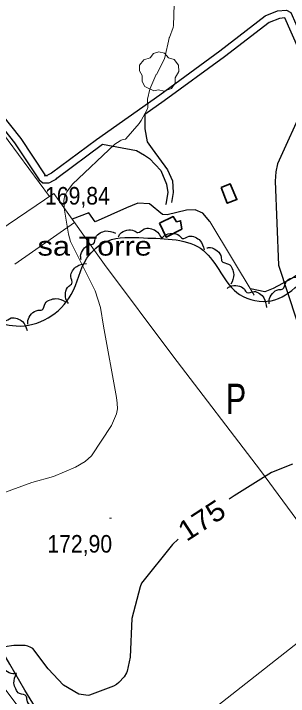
# Model space of a CAD drawing. Extents: x 480269 to 484877, y 4383588 to 4386804.
# Drawn here: x 482259.8 to 482396.3, y 4385773.1 to 4386113.1 of the extents above; entities that cross this region are included whole.
import ezdxf
from ezdxf.enums import TextEntityAlignment as Align

# ---------------------------------------------------------------- set-up
doc = ezdxf.new("R2010")
doc.units = 0
doc.header["$LTSCALE"] = 3.8
doc.linetypes.add('LONG_DASHED', pattern=[7.5, 6, -1.5])
for name, color, linetype, lineweight in [('25', 7, 'LONG_DASHED', 25), ('27', 7, 'Continuous', 25), ('29', 7, 'Continuous', 13), ('38', 7, 'Continuous', 25), ('47', 7, 'Continuous', 35), ('51', 7, 'Continuous', 13), ('7', 7, 'Continuous', 13), ('8', 7, 'Continuous', 25), ('9', 7, 'Continuous', 13)]:
    doc.layers.add(name, color=color, linetype=linetype, lineweight=lineweight)
doc.layers.add('31', color=7, linetype='Continuous')
doc.layers.add('5', color=7, linetype='Continuous')

msp = doc.modelspace()

# ---------------------------------------------------------------- linework, layer by layer
at = {"layer": '25'}
for points in [[(482357.29, 4386009.55), (482353.77, 4386013.72), (482350.05, 4386015.51), (482345.8, 4386015.31), (482336.13, 4386012.95), (482333.78, 4386013.07), (482327.37, 4386018.44), (482321.46, 4386018.81), (482315.95, 4386016.37), (482300.31, 4386009.49), (482297.2, 4386013.87), (482288.87, 4386010.87)], [(482436.54, 4386007.62), (482433.49, 4386005.54), (482426.7, 4386001.35), (482415.4, 4385992.96), (482408.62, 4385988.3), (482398.14, 4385981.17), (482388.88, 4385976.31), (482384.69, 4385974.6), (482377.49, 4385976.02)]]:
    msp.add_lwpolyline(points, dxfattribs=at)
at = {"layer": '27'}
for points in [[(482293.35, 4385990.54), (482293.11, 4385992.3), (482294.49, 4385995.84), (482297.47, 4385998.02), (482299.47, 4385998.48), (482300.59, 4386001.85), (482302.75, 4386003.92), (482305.61, 4386004.9), (482310.46, 4386003.88)], [(482311.79, 4386001.96), (482312.75, 4386003.45), (482316.08, 4386005.27), (482319.77, 4386005.02), (482321.59, 4386004.08), (482324.62, 4386005.93), (482327.6, 4386006.12), (482330.42, 4386005.03), (482333.48, 4386001.12)], [(482333.65, 4386001.49), (482334.93, 4386002.71), (482338.6, 4386003.69), (482342.12, 4386002.58), (482343.67, 4386001.23), (482347.05, 4386002.32), (482349.99, 4386001.8), (482352.48, 4386000.08), (482354.52, 4385995.56)], [(482928.34, 4385924.89), (482922.57, 4385923.15), (482885.78, 4385895.73), (482830.19, 4385870.67), (482783.99, 4385846.38), (482748.76, 4385821.32), (482700.22, 4385785.28), (482658.72, 4385739.07), (482615.66, 4385695.2), (482579.64, 4385663.09), (482560.07, 4385645.07), (482539.71, 4385649.77), (482459.85, 4385672.49), (482360.42, 4385703.82), (482306.4, 4385727.32), (482257.85, 4385789.2), (482191.3, 4385880.85), (482166.25, 4385912.96), (482169.38, 4385923.15), (482197.57, 4385932.55), (482218.71, 4385942.73), (482235.93, 4385961.53), (482260.99, 4385957.61), (482288.39, 4385973.28), (482296.22, 4385991.3), (482306.4, 4385999.91), (482324.4, 4386001.48), (482354.16, 4385995.21), (482372.16, 4385973.28), (482387.82, 4385970.15), (482414.44, 4385988.16), (482434.02, 4385990.51), (482466.12, 4385956.05), (482473.95, 4385954.08)], [(482355.85, 4385996.54), (482357.63, 4385996.64), (482361.04, 4385994.99), (482362.99, 4385991.86), (482363.29, 4385989.83), (482366.57, 4385988.45), (482368.46, 4385986.14), (482369.23, 4385983.21), (482367.84, 4385978.45)], [(482287.08, 4385968.86), (482286.05, 4385970.31), (482285.61, 4385974.07), (482287.21, 4385977.4), (482288.76, 4385978.74), (482288.17, 4385982.25), (482289.11, 4385985.08), (482291.17, 4385987.29), (482295.94, 4385988.67)], [(482386.9, 4385968.61), (482386.82, 4385970.38), (482388.47, 4385973.79), (482391.61, 4385975.73), (482393.65, 4385976.03), (482395.04, 4385979.3), (482397.35, 4385981.18), (482400.28, 4385981.94), (482405.04, 4385980.53)], [(482365.96, 4385976.33), (482367.44, 4385977.3), (482371.22, 4385977.61), (482374.49, 4385975.88), (482375.77, 4385974.28), (482379.3, 4385974.74), (482382.1, 4385973.7), (482384.23, 4385971.56), (482385.43, 4385966.75)], [(482266.9, 4385958.48), (482266.89, 4385960.25), (482268.68, 4385963.59), (482271.91, 4385965.39), (482273.95, 4385965.6), (482275.47, 4385968.82), (482277.87, 4385970.6), (482280.82, 4385971.23), (482285.52, 4385969.63)], [(482245.28, 4385959.73), (482246.46, 4385961.05), (482250.04, 4385962.31), (482253.64, 4385961.47), (482255.29, 4385960.25), (482258.58, 4385961.59), (482261.55, 4385961.29), (482264.16, 4385959.77), (482266.54, 4385955.42)], [(482261.23, 4385784.54), (482259.47, 4385784.37), (482255.98, 4385785.87), (482253.9, 4385788.92), (482253.51, 4385790.93), (482250.18, 4385792.17), (482248.19, 4385794.4), (482247.3, 4385797.29), (482248.49, 4385802.1)], [(482273.72, 4385766.79), (482271.96, 4385766.64), (482268.49, 4385768.18), (482266.44, 4385771.26), (482266.08, 4385773.28), (482262.76, 4385774.55), (482260.8, 4385776.8), (482259.95, 4385779.7), (482261.19, 4385784.51)]]:
    msp.add_spline(points, degree=3, dxfattribs=at)
at = {"layer": '29'}
msp.add_lwpolyline([(482329.56, 4386074.69), (482325.02, 4386076.81), (482323.61, 4386079.35), (482323.71, 4386082.33), (482322.34, 4386084.74), (482322.38, 4386087.49), (482324.54, 4386090.09), (482327.73, 4386091.09), (482329.38, 4386093.28), (482331.95, 4386094.11), (482334.81, 4386093.46), (482336.76, 4386091.19), (482339.57, 4386090.37), (482341.7, 4386087.52), (482341.94, 4386084.39), (482340.06, 4386081.24), (482340.06, 4386078.56), (482338.24, 4386075.95), (482334.62, 4386074.61), (482331.85, 4386075.24)], close=True, dxfattribs=at)
at = {"layer": '38'}
for points in [[(482078.56, 4386288.52), (482080.01, 4386288.01), (482080.83, 4386287.35), (482083.87, 4386282.61), (482090.69, 4386273.46), (482108.7, 4386248.97), (482130.44, 4386220.12), (482150.72, 4386192.38), (482175.14, 4386159.92), (482195.21, 4386133.53), (482218.48, 4386102.67), (482236.45, 4386078.61), (482260.25, 4386048.76), (482272.46, 4386030.42), (482274.27, 4386028.86), (482277.26, 4386028.85), (482277.85, 4386029.07), (482279.25, 4386029.86), (482280.98, 4386030.68), (482281.34, 4386031.19), (482303.95, 4386048.09)], [(482186.87, 4386150.47), (482198.21, 4386135.81), (482221.49, 4386104.93), (482239.44, 4386080.91), (482263.3, 4386050.98), (482275.3, 4386032.94), (482275.67, 4386032.62), (482276.57, 4386032.62), (482276.25, 4386032.49), (482277.53, 4386033.21), (482278.46, 4386033.65), (482278.59, 4386033.84), (482300.94, 4386050.54), (482332.49, 4386072.75), (482362.33, 4386094.67), (482384.92, 4386112.11), (482391.03, 4386114.49), (482395.38, 4386114.95), (482397.61, 4386113.78), (482405.11, 4386096.76), (482415.34, 4386072.09), (482423.59, 4386050.46)], [(482420.07, 4386049.12), (482411.84, 4386070.7), (482401.65, 4386095.28), (482394.69, 4386111.06), (482394.64, 4386111.08), (482391.92, 4386110.8), (482386.79, 4386108.8), (482364.59, 4386091.66), (482334.69, 4386069.69), (482324.97, 4386062.85)], [(482324.97, 4386062.85), (482324.95, 4386055.77), (482326.14, 4386049.28), (482328.71, 4386045.87), (482336.21, 4386035.41), (482338.77, 4386029.91), (482339.13, 4386024.09), (482338.35, 4386019.15)], [(482303.95, 4386048.09), (482320.79, 4386045.06), (482324.84, 4386042.62), (482327.4, 4386041), (482333.01, 4386035.09), (482335.72, 4386028.24), (482336.38, 4386024.03), (482335.42, 4386018.19), (482335.34, 4386017.97)]]:
    msp.add_lwpolyline(points, dxfattribs=at)
at = {"layer": '47'}
for points in [[(482362.94, 4386026.58), (482366.02, 4386018.74), (482370.77, 4386020.57), (482367.46, 4386028.32)], [(482332.24, 4386008.76), (482335.63, 4386001.78), (482343.45, 4386005.86), (482342.78, 4386010.01), (482340.77, 4386009.5), (482339.18, 4386012.04)]]:
    msp.add_lwpolyline(points, close=True, dxfattribs=at)
at = {"layer": '51'}
for p, q in [((482260.41, 4385988.43), (482290.08, 4386009.17)), ((482379.34, 4385972.93), (482357.29, 4386009.55))]:
    msp.add_line(p, q, dxfattribs=at)
for points in [[(482277.59, 4386022.06), (482221, 4386098.74), (482171.74, 4386163.91), (482120.88, 4386231.42), (482079.09, 4386287.6), (482069.79, 4386283.22), (482063.21, 4386279.39), (482053.77, 4386273.42), (482051.37, 4386270.92), (482041.47, 4386257.57), (482026.53, 4386237.69), (482023.67, 4386235.19), (482025.03, 4386230.05), (482025.68, 4386229.13)], [(482779.62, 4386098.45), (482742.85, 4386070.07), (482699.48, 4386036.34), (482644.98, 4385992.23), (482611.45, 4385965.76), (482554.45, 4385920.69), (482472.77, 4385856.39), (482299.35, 4385719.82), (482274.18, 4385752.03), (482255.92, 4385776.25), (482234.75, 4385804.89), (482209.61, 4385837.32), (482152.61, 4385914.04), (482157.42, 4385920.91)], [(482248.04, 4386002.15), (482279.82, 4386023.56), (482305.02, 4385988.19), (482338.87, 4385942.79), (482382.48, 4385885.67), (482429.24, 4385822.11)]]:
    msp.add_lwpolyline(points, dxfattribs=at)
at = {"layer": '7'}
for p, q in [((482274.9, 4386032.44), (482275.9, 4386032.44)), ((482307.49, 4385861.89), (482308.49, 4385861.89))]:
    msp.add_line(p, q, dxfattribs=at)
at = {"layer": '8'}
for points in [[(482404.43, 4386067.95), (482391.04, 4386038.38), (482390.1, 4386034.31), (482389.78, 4386029.7), (482391.51, 4385987.89), (482414.06, 4385919.27)], [(482398.41, 4385888.76), (482388.03, 4385884.6), (482369.44, 4385873.04), (482366.96, 4385871.27)], [(482341.64, 4385851.42), (482338.8, 4385848.73), (482323.35, 4385829.58), (482322.66, 4385827.7), (482318.62, 4385811.98), (482317.78, 4385792.65), (482316.3, 4385785.61), (482315.91, 4385784.78), (482314.68, 4385782.92), (482312.11, 4385780.05), (482310.96, 4385779.04)], [(482296.87, 4385773.49), (482292.16, 4385774.21), (482284.57, 4385778.71), (482276.99, 4385786.85), (482269.32, 4385797.02), (482268.37, 4385797.52), (482266.81, 4385798.13), (482265.45, 4385798.41), (482259.85, 4385798.39), (482255.48, 4385797.85), (482252.53, 4385796.92), (482210.17, 4385771.58)], [(482310.96, 4385779.04), (482309.41, 4385778.15), (482297.45, 4385773.64), (482296.87, 4385773.49)]]:
    msp.add_lwpolyline(points, dxfattribs=at)
at = {"layer": '9'}
msp.add_lwpolyline([(482240.63, 4385869.34), (482268.79, 4385879.66), (482279.61, 4385882.6), (482290.56, 4385887.32), (482295.31, 4385890.17), (482298.47, 4385892.87), (482308.48, 4385908.02), (482308.5, 4385908.08), (482310.89, 4385913.82), (482311.35, 4385916.28), (482311.36, 4385916.38), (482311.33, 4385919.14), (482311, 4385921.97), (482304.53, 4385957.46), (482302.99, 4385966.76), (482300.27, 4385975.08), (482300.27, 4385975.09), (482300.24, 4385975.16), (482288.09, 4385999.71), (482287.1, 4386003.3), (482284.92, 4386016.32), (482284.78, 4386020.12), (482284.85, 4386020.87), (482285.1, 4386021.88), (482285.38, 4386022.67), (482286.23, 4386024.32), (482288.97, 4386028.3), (482310.04, 4386048.07), (482312.72, 4386049.81), (482313.3, 4386050.09), (482314.27, 4386050.42), (482315.32, 4386050.66), (482315.57, 4386050.74), (482322.17, 4386058.39), (482323.13, 4386059.89), (482326.21, 4386065.35), (482326.4, 4386065.85), (482326.47, 4386066.27), (482326.46, 4386066.64), (482326.28, 4386069.93), (482326.31, 4386070.54), (482327.42, 4386075.59), (482330.46, 4386082.53), (482330.53, 4386082.64), (482330.76, 4386082.89), (482334.77, 4386090.61), (482336.51, 4386097.91), (482336.72, 4386099.48), (482337.15, 4386101.07), (482337.2, 4386101.21), (482339.02, 4386106.32), (482339.24, 4386107.24), (482340.03, 4386133.6)], dxfattribs=at)

# ---------------------------------------------------------------- texts
at = {"layer": '31', "width": 0.75}
msp.add_text('P', height=15, dxfattribs=at).set_placement((482370.38, 4385913.83), align=Align.CENTER)
at = {"layer": '5', "width": 1.2}
msp.add_text('sa Torre', height=9.5, dxfattribs=at).set_placement((482328.46, 4385992.64), align=Align.RIGHT)
at = {"layer": '7', "width": 0.9}
for s, p in [('169,84', (482275.4, 4386018.07)), ('172,90', (482276.54, 4385844.72))]:
    msp.add_text(s, height=8.75, dxfattribs=at).set_placement(p)
at = {"layer": '8', "width": 1.1}
msp.add_text('175', height=9.999, rotation=33.019, dxfattribs=at).set_placement((482355.98, 4385856.63), align=Align.CENTER)

doc.saveas('drawing.dxf')
